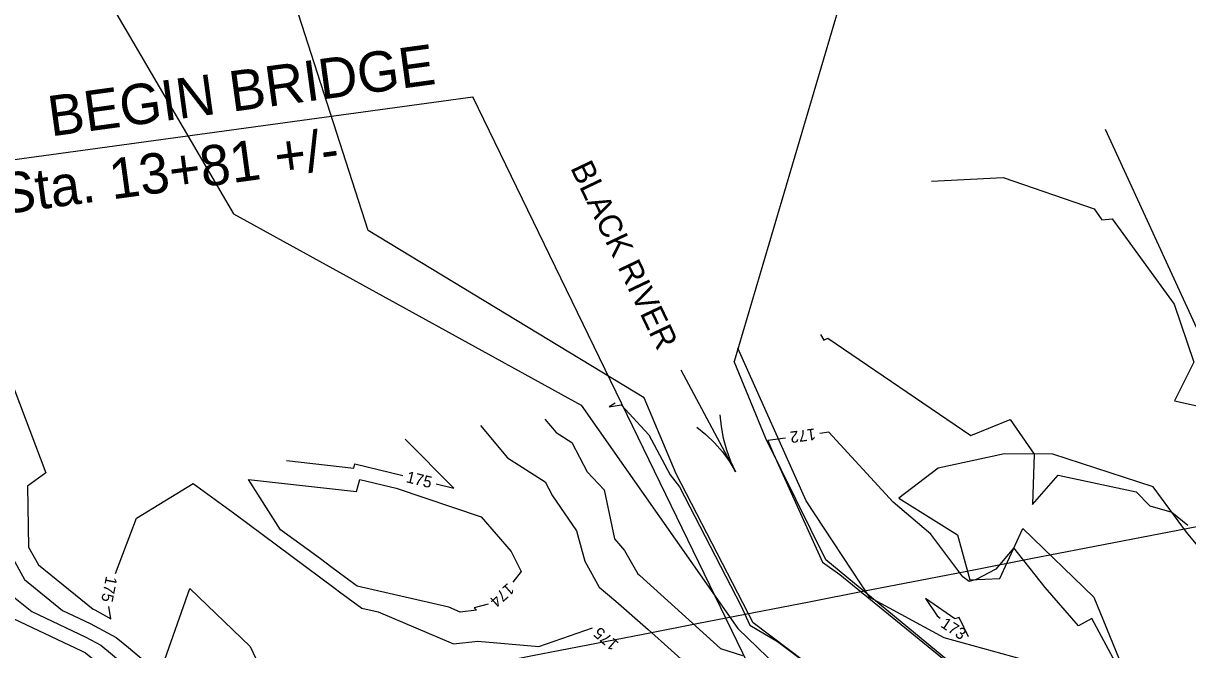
# Model space of a CAD drawing. Extents: x 2086416 to 2115205, y 575507 to 632762.
# Drawn here: x 2111355.3 to 2111557.3, y 581693.8 to 581802.4 of the extents above; entities that cross this region are included whole.
import ezdxf

# ---------------------------------------------------------------- set-up
doc = ezdxf.new("R2010")
doc.units = 0
for name, color, linetype in [('DTM Contours Major', 7, 'Continuous'), ('DTM Contours Major Text', 7, 'Continuous'), ('DTM Contours Minor', 7, 'Continuous'), ('DTM Contours Minor Text', 7, 'Continuous'), ('Exist Hydro River Flow Arrow CELL', 7, 'Continuous'), ('Exist Hydro Stream or Body of Water', 7, 'Continuous'), ('Exist Hydro Stream or Body of Water Text', 7, 'Continuous'), ('Exist Hydrographic FEMA Cross Section', 7, 'Continuous'), ('Exist Right of Way Line', 7, 'Continuous'), ('Exist Vegetation Woods Line', 7, 'Continuous'), ('Prop Horizontal Alignment Station Label', 7, 'Continuous')]:
    doc.layers.add(name, color=color, linetype=linetype)

msp = doc.modelspace()

# ---------------------------------------------------------------- linework, layer by layer
at = {"layer": 'DTM Contours Major'}
for points in [[(2111336.48, 581784.42), (2111359.19, 581724.48), (2111356.03, 581722.18), (2111356.22, 581711.58), (2111357.93, 581708.49), (2111367.42, 581700.82), (2111367.7, 581700.69), (2111370.5, 581699.17), (2111370.16, 581701.31)], [(2111426.96, 581722.58), (2111429.99, 581721.84), (2111421.58, 581730.33)], [(2111400.94, 581726.62), (2111412.63, 581725.3), (2111412.83, 581726.02), (2111421.13, 581724)], [(2111371.28, 581707.03), (2111374.93, 581716.64), (2111384.78, 581722.6), (2111391.79, 581717.51), (2111409.44, 581704.41), (2111410.19, 581703.86), (2111414.03, 581701.01), (2111416.85, 581700.36), (2111429.92, 581694.81), (2111434.18, 581695.3), (2111444.75, 581694.38), (2111454.06, 581697.6)]]:
    msp.add_lwpolyline(points, dxfattribs=at)
at = {"layer": 'DTM Contours Minor'}
for points in [[(2111512.86, 581775.08), (2111525.32, 581775.7), (2111541.08, 581770.28), (2111542.43, 581768.36), (2111544.24, 581768.53), (2111554.95, 581753.72), (2111558.4, 581743.64), (2111555.04, 581736.97), (2111563.15, 581735.16)], [(2111260.91, 581756.14), (2111260.56, 581753.66), (2111263.25, 581749.57), (2111272.06, 581734.37), (2111271.17, 581754.63), (2111289.23, 581762.28), (2111298.09, 581762.28), (2111340.41, 581719.17), (2111341.02, 581718.36), (2111341.03, 581718.18), (2111350.61, 581700.9), (2111351.45, 581700.22), (2111365.39, 581693.62), (2111366.1, 581693.23), (2111372.81, 581687.77), (2111373.33, 581687.33), (2111373.12, 581686.65), (2111370.29, 581684.39), (2111374.42, 581679.53), (2111381.41, 581682.41)], [(2111493.59, 581748.45), (2111494.22, 581747.49), (2111494.87, 581747.84), (2111519.72, 581730.97), (2111526.54, 581733.72), (2111530.69, 581727.73), (2111530.4, 581718.98), (2111534.84, 581724.07), (2111548.37, 581721.16), (2111550.74, 581718.74), (2111554.56, 581717.65), (2111557.36, 581715.39)], [(2111457.98, 581736.54), (2111456.92, 581735.92), (2111459.05, 581736.25), (2111463.83, 581731.09), (2111467.55, 581724.13), (2111469.15, 581722.04), (2111479.82, 581701.48), (2111481.33, 581698.06), (2111486.15, 581695.2), (2111501.55, 581683.63)], [(2111445.79, 581733.8), (2111447.75, 581731.48), (2111450.45, 581729.75), (2111453.11, 581724.62), (2111456.1, 581721.51), (2111457.9, 581713.03), (2111459.62, 581711.02), (2111461.92, 581706.93), (2111462.2, 581706.7), (2111462.27, 581706.64), (2111476.24, 581694.01), (2111480.08, 581692.79)], [(2111434.62, 581732.71), (2111439.32, 581727.1), (2111445.84, 581722.92), (2111447.1, 581720.51), (2111451.31, 581714.39), (2111452.73, 581709.15), (2111455.2, 581704.64), (2111458.13, 581702.19), (2111463.73, 581697.33), (2111471.7, 581690.12)], [(2111548.2, 581671.64), (2111548.49, 581671.78), (2111551.1, 581675.47), (2111552.12, 581677.61), (2111547.4, 581686.58), (2111547.31, 581686.83), (2111540.68, 581699.19), (2111538.37, 581697.96), (2111532.61, 581704.59), (2111527.17, 581711.48), (2111524.03, 581707.75), (2111520.62, 581705.98), (2111519.42, 581705.65), (2111518.28, 581706.43), (2111512.75, 581713.86), (2111506.23, 581719.41), (2111495.05, 581731.52), (2111493.49, 581731.31)], [(2111487.55, 581730.5), (2111484.48, 581730.08), (2111485.47, 581727.76), (2111493.95, 581708.99), (2111496.97, 581706.84), (2111514.48, 581692.55), (2111515.67, 581691.69), (2111524.2, 581685.01), (2111533.54, 581678.42), (2111534.65, 581678.5), (2111535.24, 581677.74), (2111541.52, 581673.5), (2111544.74, 581671.76), (2111547.52, 581671.58), (2111548.2, 581671.64)], [(2111394.37, 581723.34), (2111413.12, 581721.23), (2111413.68, 581723.34), (2111420, 581721.8), (2111434.73, 581716.85), (2111439.94, 581710.81), (2111441.68, 581707.35), (2111440.23, 581705.54)], [(2111435.93, 581701.69), (2111433.51, 581701.04), (2111433.92, 581700.63), (2111431.11, 581700.31), (2111429.12, 581701.15), (2111413.22, 581704.84), (2111412.61, 581705.3), (2111408.86, 581708.03), (2111406.84, 581709.53), (2111399.91, 581714.57), (2111394.37, 581723.34)], [(2111351.15, 581713.78), (2111355.49, 581705.96), (2111362.1, 581700.62), (2111366.93, 581698.33), (2111371.43, 581695.89), (2111373.55, 581694.16), (2111376.52, 581691.68), (2111379.54, 581691.09), (2111384.17, 581704.43), (2111394.67, 581694.38), (2111399.03, 581685.14), (2111401.95, 581684.57), (2111403.47, 581684.17), (2111414.91, 581679.96), (2111416.1, 581679.4), (2111419.93, 581678.31), (2111420.71, 581678.72), (2111421.55, 581678.53), (2111422.97, 581678.9)], [(2111353.05, 581703.43), (2111356.77, 581700.42), (2111366.16, 581695.97), (2111368.76, 581694.56), (2111373.18, 581690.97)], [(2111516.93, 581699.16), (2111511.81, 581702.65), (2111513.85, 581699.7), (2111514.38, 581699.27)], [(2111519.3, 581696.05), (2111517.68, 581699.36), (2111516.93, 581699.16)]]:
    msp.add_lwpolyline(points, dxfattribs=at)
at = {"layer": 'Exist Hydro River Flow Arrow CELL'}
for p, q in [((2111478.89, 581724.66), (2111469.43, 581742.29)), ((2111474.16, 581733.47), (2111474.16, 581733.47)), ((2111476.17, 581734.56), (2111476.37, 581732.52)), ((2111472.14, 581732.39), (2111473.73, 581731.1)), ((2111473.73, 581731.1), (2111475.22, 581729.66)), ((2111476.37, 581732.52), (2111476.74, 581730.48)), ((2111475.22, 581729.66), (2111476.61, 581728.09)), ((2111476.74, 581730.48), (2111477.29, 581728.46)), ((2111476.61, 581728.09), (2111477.85, 581726.43)), ((2111477.29, 581728.46), (2111477.98, 581726.5)), ((2111477.85, 581726.43), (2111478.89, 581724.66)), ((2111477.98, 581726.5), (2111478.89, 581724.66))]:
    msp.add_line(p, q, dxfattribs=at)
at = {"layer": 'Exist Hydro Stream or Body of Water'}
for points in [[(2111463, 581737.48), (2111415.11, 581766.53), (2111397.64, 581820.96), (2111352.3, 581841.23), (2111333.83, 581869.49), (2111330, 581879.12), (2111337.82, 581902), (2111329.78, 581919.05), (2111313.88, 581938.09), (2111294.11, 581978.61), (2111295.93, 582000.43), (2111293.88, 582015.55), (2111285.78, 582045.07), (2111284.37, 582067.54), (2111288.67, 582094.58), (2111287.89, 582112.99), (2111281.07, 582150.07), (2111274.06, 582190.6)], [(2111453.09, 582094.1), (2111443.96, 582082.97), (2111447.94, 582071.29), (2111430.65, 582047.36), (2111437.21, 582014.64), (2111436.6, 581990.7), (2111456.37, 581961.91), (2111482.37, 581945.66), (2111482.01, 581910.08), (2111498.18, 581892.27), (2111507.18, 581840.49), (2111478.63, 581743.8)], [(2111571.77, 581696.53), (2111557.1, 581714.2), (2111551.35, 581722.03), (2111533.92, 581727.7), (2111525.55, 581727.77), (2111514.02, 581725.29), (2111507.22, 581720.09), (2111517.38, 581713.7), (2111519.53, 581705.93), (2111524.72, 581706.16), (2111528.7, 581714.8), (2111541.06, 581702.9), (2111547.6, 581686.8), (2111552.73, 581677.36), (2111547.95, 581671.83), (2111544.85, 581671.93), (2111533.91, 581677.08), (2111514.73, 581692.74), (2111494.53, 581709.36), (2111484.15, 581730.44), (2111478.63, 581743.8)], [(2111591.59, 581574.69), (2111583.51, 581582.32), (2111586.65, 581587.28), (2111586.9, 581588.76), (2111586.51, 581589.98), (2111561.57, 581606.34), (2111549, 581629.07), (2111542.47, 581641.26), (2111541.35, 581641.18), (2111528.82, 581652.89), (2111524.36, 581663.91), (2111523.31, 581667.75), (2111502.68, 581682.78), (2111481.94, 581698.46), (2111468.58, 581724.28), (2111463, 581737.48)]]:
    msp.add_lwpolyline(points, dxfattribs=at)
at = {"layer": 'Exist Hydrographic FEMA Cross Section'}
msp.add_lwpolyline([(2111558.92, 581715.13), (2111549.31, 581713.26), (2111539.7, 581711.4), (2111530.09, 581709.53), (2111520.48, 581707.66), (2111510.88, 581705.79), (2111501.27, 581703.93), (2111491.66, 581702.06), (2111482.06, 581700.19), (2111472.45, 581698.32), (2111462.84, 581696.46), (2111453.23, 581694.59), (2111443.62, 581692.72), (2111434.02, 581690.85), (2111424.41, 581688.98), (2111414.8, 581687.11), (2111405.19, 581685.25), (2111395.59, 581683.38), (2111385.98, 581681.51), (2111376.37, 581679.64), (2111366.77, 581677.77), (2111357.16, 581675.91), (2111347.55, 581674.04)], dxfattribs=at)
at = {"layer": 'Exist Right of Way Line'}
msp.add_arc((2108326.55, 606231.5), 24756.94, 277.393911, 277.856215, dxfattribs=at)
at = {"layer": 'Exist Vegetation Woods Line'}
for points in [[(2111262.29, 582184.02), (2111265.31, 582083.43), (2111279.98, 581987.09), (2111311.55, 581918.74), (2111324.25, 581867.33), (2111346.25, 581833.12), (2111371.51, 581803.94), (2111391.8, 581769.41), (2111452.1, 581736.22)], [(2111543, 581784.1), (2111565.77, 581734.52), (2111587.19, 581707.45), (2111708.99, 581713.78), (2111811.99, 581727.73), (2111909.41, 581740.4), (2112007.41, 581746.55), (2112041.96, 581749.79), (2112042.22, 581740.22)], [(2112042.22, 581740.22), (2112007.09, 581741.23), (2111957.14, 581737.86), (2111908.66, 581731.85), (2111808.65, 581718.24), (2111760.41, 581712.7), (2111710.34, 581706.77), (2111661.65, 581697.22), (2111616.66, 581692.44), (2111575, 581689.29), (2111546.91, 581687.08), (2111515.04, 581695.86), (2111502.17, 581702.85), (2111491.11, 581719.62), (2111479.28, 581746.11)], [(2111452.1, 581736.22), (2111479.27, 581697.5), (2111499.68, 581677.78), (2111492.04, 581671.34), (2111416.64, 581665.13), (2111367.28, 581660.93), (2111318.17, 581654.2), (2111268.32, 581650.61), (2111220.66, 581649.45), (2111173.29, 581649.12), (2111125.98, 581651.57), (2111078.27, 581655.72), (2111059.79, 581657.65)]]:
    msp.add_lwpolyline(points, dxfattribs=at)
at = {"layer": 'Prop Horizontal Alignment Station Label'}
for p in [(2111302.64, 581771.83), (2111502.04, 581648.05)]:
    msp.add_line(p, (2111433.3, 581789.66), dxfattribs=at)

# ---------------------------------------------------------------- texts
at = {"layer": 'DTM Contours Major Text'}
for rotation, p in [(346.3238, (2111421.6, 581722.86)), (258.92, (2111369.67, 581706.65)), (139.5891, (2111458.73, 581694.98))]:
    msp.add_text('175', height=2, rotation=rotation, dxfattribs=at).set_placement(p)
at = {"layer": 'DTM Contours Minor Text'}
for s, rotation, p in [('172', 187.7686, (2111492.64, 581732.2)), ('174', 221.8811, (2111439.38, 581705.46)), ('173', 326.7687, (2111514.3, 581697.85))]:
    msp.add_text(s, height=2, rotation=rotation, dxfattribs=at).set_placement(p)
at = {"layer": 'Exist Hydro Stream or Body of Water Text'}
msp.add_text('BLACK RIVER', height=4, rotation=295.5556, dxfattribs=at).set_placement((2111450.15, 581777.37))
at = {"layer": 'Prop Horizontal Alignment Station Label'}
for s, p in [('BEGIN BRIDGE', (2111360.1, 581782.8)), ('-L- POT Sta. 13+81 +/-  ', (2111316.09, 581764.43))]:
    msp.add_text(s, height=7, rotation=7.771, dxfattribs=at).set_placement(p)

doc.saveas('drawing.dxf')
